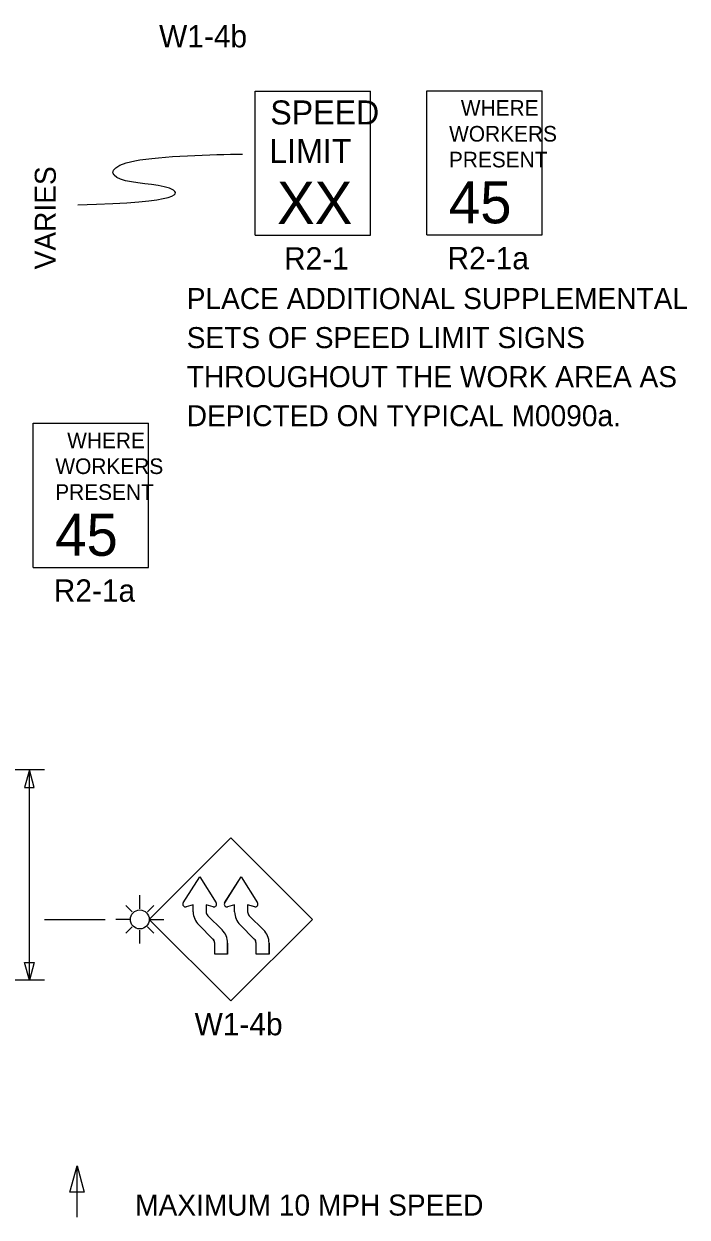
# Model space of a CAD drawing. Extents: x 16544 to 19504, y 5662 to 6922.
# Drawn here: x 17196.2 to 17417.1, y 6075.6 to 6473 of the extents above; entities that cross this region are included whole.
import ezdxf

# ---------------------------------------------------------------- set-up
doc = ezdxf.new("R2010")
doc.units = 0
doc.layers.add('TRAFFIC_SIGNS_PR', color=7, linetype='Continuous')
doc.layers.add('TYPICAL_TEXT_DIMEN_PR', color=7, linetype='Continuous')

msp = doc.modelspace()

# ---------------------------------------------------------------- linework, layer by layer
at = {"layer": 'TRAFFIC_SIGNS_PR'}
for p, q in [((17273.26, 6450.59), (17311.66, 6450.59)), ((17273.26, 6402.59), (17273.26, 6450.59)), ((17311.66, 6402.59), (17311.66, 6450.59)), ((17330.45, 6450.67), (17368.85, 6450.67)), ((17330.45, 6402.67), (17330.45, 6450.67)), ((17368.85, 6402.67), (17368.85, 6450.67)), ((17273.26, 6402.59), (17311.66, 6402.59)), ((17330.45, 6402.67), (17368.85, 6402.67)), ((17199.32, 6339.98), (17237.72, 6339.98)), ((17199.32, 6291.98), (17199.32, 6339.98)), ((17237.72, 6291.98), (17237.72, 6339.98)), ((17199.32, 6291.98), (17237.72, 6291.98)), ((17237.98, 6174.75), (17265.14, 6201.9)), ((17265.14, 6201.9), (17292.29, 6174.75)), ((17234.83, 6178.31), (17234.83, 6182.81)), ((17232.32, 6177.26), (17230.21, 6179.37)), ((17237.34, 6177.26), (17239.45, 6179.37)), ((17231.68, 6174.75), (17226.84, 6174.75)), ((17237.98, 6174.75), (17242.87, 6174.75)), ((17265.14, 6147.6), (17237.98, 6174.75)), ((17262.21, 6171.28), (17257.49, 6176)), ((17257.49, 6176), (17262.21, 6171.28)), ((17292.29, 6174.75), (17265.14, 6147.6)), ((17276, 6171.28), (17271.29, 6176)), ((17271.29, 6176), (17276, 6171.28)), ((17232.32, 6172.24), (17230.21, 6170.13)), ((17234.83, 6166.78), (17234.83, 6171.2)), ((17237.34, 6172.24), (17239.45, 6170.13)), ((17259.16, 6168.23), (17254.44, 6172.95)), ((17259.15, 6168.23), (17254.44, 6172.95)), ((17272.95, 6168.23), (17268.24, 6172.95)), ((17272.95, 6168.23), (17268.24, 6172.95)), ((17259.76, 6163.16), (17259.76, 6166.86)), ((17264.07, 6163.16), (17264.07, 6166.86)), ((17273.55, 6163.16), (17273.55, 6166.86)), ((17277.87, 6163.16), (17277.87, 6166.86)), ((17264.07, 6163.16), (17259.76, 6163.16)), ((17277.87, 6163.16), (17273.55, 6163.16))]:
    msp.add_line(p, q, dxfattribs=at)
for points in [[(17249.29, 6180.27), (17254.77, 6188.88), (17260.25, 6180.27)], [(17249.29, 6180.27), (17254.77, 6188.88), (17260.25, 6180.27)], [(17263.08, 6180.27), (17268.57, 6188.88), (17274.05, 6180.27)], [(17263.09, 6180.27), (17268.57, 6188.88), (17274.05, 6180.27)], [(17252.62, 6177.26), (17252.61, 6179.62), (17250.25, 6178.98)], [(17252.62, 6177.26), (17252.61, 6179.62), (17250.25, 6178.98)], [(17259.29, 6178.98), (17256.93, 6179.62), (17256.93, 6177.33)], [(17259.29, 6178.97), (17258.46, 6179.2), (17256.93, 6179.62), (17256.93, 6177.33)], [(17266.41, 6177.26), (17266.41, 6179.62), (17264.05, 6178.98)], [(17266.41, 6177.26), (17266.41, 6179.62), (17264.05, 6178.98)], [(17273.09, 6178.98), (17270.73, 6179.62), (17270.73, 6177.33)], [(17273.09, 6178.97), (17272.25, 6179.2), (17270.73, 6179.62), (17270.73, 6177.33)], [(17264.08, 6166.86), (17264.07, 6163.16), (17259.76, 6163.16), (17259.76, 6166.86)], [(17277.87, 6166.86), (17277.87, 6163.16), (17273.55, 6163.16), (17273.55, 6166.86)]]:
    msp.add_lwpolyline(points, dxfattribs=at)
msp.add_circle((17234.83, 6174.75), 3.15, dxfattribs=at)
for centre, radius, start, end in [((17250.02, 6179.81), 0.866, 147.7292, 285.3172), ((17250.02, 6179.81), 0.866, 147.7196, 285.3201), ((17240.18, 6186.07), 10.8, 327.5335, 327.5431), ((17253.1, 6168.56), 10.8, 105.3192, 105.32), ((17259.52, 6179.81), 0.864, 254.6014, 32.4796), ((17259.52, 6179.81), 0.866, 254.6148, 32.4712), ((17263.82, 6179.81), 0.866, 147.7292, 285.3172), ((17263.82, 6179.81), 0.866, 147.7196, 285.3201), ((17253.97, 6186.07), 10.8, 327.5335, 327.5431), ((17266.9, 6168.56), 10.8, 105.3192, 105.32), ((17273.32, 6179.81), 0.864, 254.6014, 32.4796), ((17273.32, 6179.81), 0.866, 254.6148, 32.4712), ((17258.78, 6177.32), 6.17, 180.6181, 225.7875), ((17258.78, 6177.33), 6.17, 180.6245, 225.2313), ((17258.78, 6177.33), 1.85, 179.8762, 225.7877), ((17258.78, 6177.32), 1.85, 180, 225.7875), ((17272.58, 6177.32), 6.17, 180.6181, 225.7875), ((17272.58, 6177.33), 6.17, 180.6245, 225.2313), ((17272.58, 6177.33), 1.85, 179.8762, 225.7877), ((17272.58, 6177.32), 1.85, 180, 225.7875), ((17257.91, 6166.86), 6.17, 0, 45.7883), ((17257.91, 6166.86), 6.17, 0, 45.7875), ((17257.91, 6166.86), 6.17, 0, 45.7875), ((17271.71, 6166.86), 6.17, 0, 45.7875), ((17271.71, 6166.86), 6.17, 0, 45.7875), ((17271.7, 6166.86), 6.17, 0, 45.7883), ((17257.91, 6166.86), 1.85, 0, 47.628), ((17257.91, 6166.86), 1.85, 0, 45.7875), ((17271.7, 6166.86), 1.85, 0, 47.628), ((17271.71, 6166.86), 1.85, 0, 45.7875)]:
    msp.add_arc(centre, radius, start, end, dxfattribs=at)
at = {"layer": 'TYPICAL_TEXT_DIMEN_PR'}
for p, q in [((17203.04, 6224.56), (17094.92, 6224.56)), ((17198.04, 6224.56), (17196.47, 6218.7)), ((17198.04, 6154.56), (17198.04, 6224.56)), ((17199.61, 6218.7), (17198.04, 6224.56)), ((17196.47, 6218.7), (17198.04, 6218.7)), ((17198.04, 6218.7), (17199.61, 6218.7)), ((17223.26, 6174.56), (17203.04, 6174.56)), ((17198.04, 6154.56), (17196.47, 6160.43)), ((17196.47, 6160.43), (17198.04, 6160.43)), ((17198.04, 6160.43), (17199.61, 6160.43)), ((17199.61, 6160.43), (17198.04, 6154.56)), ((17203.04, 6154.56), (17094.92, 6154.56)), ((17211.57, 6083.95), (17213.93, 6092.74)), ((17213.93, 6075.62), (17213.93, 6092.74)), ((17213.93, 6092.74), (17216.28, 6083.95)), ((17213.93, 6083.95), (17211.57, 6083.95)), ((17216.28, 6083.95), (17213.93, 6083.95))]:
    msp.add_line(p, q, dxfattribs=at)
msp.add_open_spline([(17214.19, 6412.71), (17249.54, 6413.53), (17248.38, 6419.75), (17224.46, 6419.75), (17224.46, 6428.58), (17259.22, 6429.48), (17268.98, 6429.6)], degree=3, dxfattribs=at)

# ---------------------------------------------------------------- texts
at = {"layer": 'TRAFFIC_SIGNS_PR'}
for s, height, p in [('W1-4b', 7.44, (17241.25, 6465.12)), ('SPEED', 8, (17278.29, 6439.45)), ('WHERE', 5.2, (17341.76, 6442.36)), ('WORKERS', 5.2, (17337.84, 6433.76)), ('LIMIT', 8, (17277.96, 6426.65)), ('PRESENT', 5.2, (17337.77, 6425.16)), ('XX', 14.031, (17280.56, 6406.34)), ('45', 14.031, (17337.76, 6406.53)), ('R2-1', 7.44, (17282.87, 6391.15)), ('R2-1a', 7.44, (17337.31, 6391.23)), ('PLACE ADDITIONAL SUPPLEMENTAL', 7, (17250.45, 6377.98)), ('SETS OF SPEED LIMIT SIGNS', 7, (17250.45, 6364.98)), ('THROUGHOUT THE WORK AREA AS', 7, (17250.45, 6351.98)), ('DEPICTED ON TYPICAL M0090a.', 7, (17250.45, 6338.98)), ('WHERE', 5.2, (17210.63, 6331.66)), ('WORKERS', 5.2, (17206.71, 6323.06)), ('PRESENT', 5.2, (17206.64, 6314.46)), ('45', 14.031, (17206.63, 6295.83)), ('R2-1a', 7.44, (17206.18, 6280.54)), ('W1-4b', 7.44, (17253.09, 6136.16))]:
    msp.add_text(s, height=height, dxfattribs=at).set_placement(p)
at = {"layer": 'TYPICAL_TEXT_DIMEN_PR'}
msp.add_text('VARIES', height=7, rotation=90, dxfattribs=at).set_placement((17206.85, 6391.19))
msp.add_text('MAXIMUM 10 MPH SPEED', height=7, dxfattribs=at).set_placement((17233.28, 6076.13))

doc.saveas('drawing.dxf')
